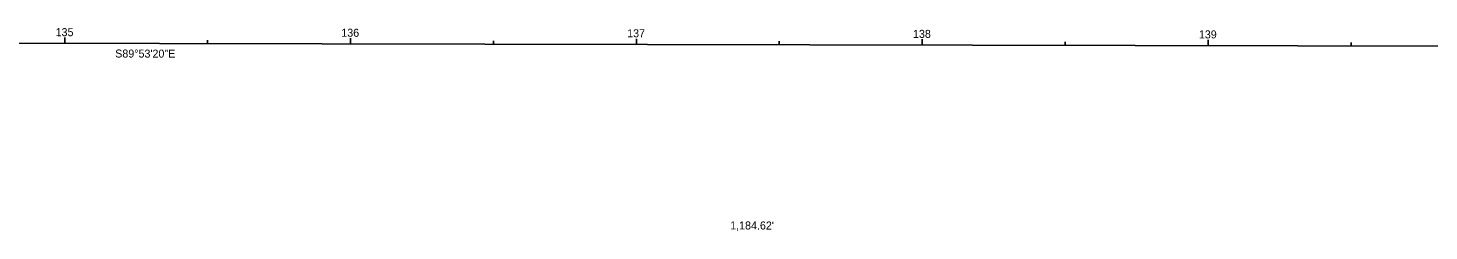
# Model space of a CAD drawing. Extents: x 1501024 to 1508874, y 327839 to 328839.
# Drawn here: x 1501514.6 to 1502004.7, y 328386 to 328456.9 of the extents above; entities that cross this region are included whole.
import ezdxf

# ---------------------------------------------------------------- set-up
doc = ezdxf.new("R2010")
doc.units = 0
for name, color, linetype in [('GE_X_Alignment', 7, 'Continuous'), ('GE_X_Alignment_100_Bearings', 7, 'Continuous'), ('GE_X_Alignment_100_Distances', 7, 'Continuous'), ('GE_X_Alignment_100_Stations', 7, 'Continuous'), ('GE_X_Alignment_500_Bearings', 7, 'Continuous'), ('GE_X_Alignment_500_Distances', 7, 'Continuous'), ('GE_X_Alignment_500_Stations', 7, 'Continuous')]:
    doc.layers.add(name, color=color, linetype=linetype)

msp = doc.modelspace()

# ---------------------------------------------------------------- linework, layer by layer
at = {"layer": 'GE_X_Alignment'}
msp.add_line((1501027.44, 328452.53), (1502212.06, 328450.23), dxfattribs=at)
at = {"layer": 'GE_X_Alignment_100_Stations'}
for p, q in [((1501527.44, 328451.56), (1501527.44, 328453.56)), ((1501577.44, 328451.46), (1501577.44, 328452.66)), ((1501627.44, 328451.37), (1501627.44, 328453.37)), ((1501677.44, 328451.27), (1501677.44, 328452.47)), ((1501727.44, 328451.17), (1501727.44, 328453.17)), ((1501777.44, 328451.07), (1501777.44, 328452.27)), ((1501827.44, 328450.98), (1501827.44, 328452.98)), ((1501877.44, 328450.88), (1501877.44, 328452.08)), ((1501927.44, 328450.78), (1501927.44, 328452.78)), ((1501977.44, 328450.69), (1501977.44, 328451.89))]:
    msp.add_line(p, q, dxfattribs=at)
at = {"layer": 'GE_X_Alignment_500_Stations'}
for p, q in [((1501527.44, 328451.56), (1501527.44, 328453.56)), ((1501627.44, 328451.37), (1501627.44, 328452.57)), ((1501727.44, 328451.17), (1501727.44, 328452.37)), ((1501827.44, 328450.98), (1501827.44, 328452.18)), ((1501927.44, 328450.78), (1501927.44, 328451.98))]:
    msp.add_line(p, q, dxfattribs=at)

# ---------------------------------------------------------------- texts
at = {"layer": 'GE_X_Alignment_100_Bearings'}
msp.add_text('S89°53\'20"E', height=2.8, rotation=359.889, dxfattribs=at).set_placement((1501545.09, 328446.6))
at = {"layer": 'GE_X_Alignment_100_Distances'}
msp.add_text("1,184.62'", height=2.8, rotation=359.889, dxfattribs=at).set_placement((1501760.24, 328386.54))
at = {"layer": 'GE_X_Alignment_100_Stations'}
for s, p in [('135', (1501524.24, 328454.07)), ('136', (1501624.19, 328453.87)), ('137', (1501724.2, 328453.68)), ('138', (1501824.2, 328453.48)), ('139', (1501924.22, 328453.29))]:
    msp.add_text(s, height=2.8, rotation=359.889, dxfattribs=at).set_placement(p)
at = {"layer": 'GE_X_Alignment_500_Bearings'}
msp.add_text('S89°53\'20"E', height=2.8, rotation=359.889, dxfattribs=at).set_placement((1501545.09, 328446.6))
at = {"layer": 'GE_X_Alignment_500_Distances'}
msp.add_text("1,184.62'", height=2.8, rotation=359.889, dxfattribs=at).set_placement((1501760.24, 328386.54))
at = {"layer": 'GE_X_Alignment_500_Stations'}
msp.add_text('135', height=2.8, rotation=359.889, dxfattribs=at).set_placement((1501524.24, 328454.07))

doc.saveas('drawing.dxf')
